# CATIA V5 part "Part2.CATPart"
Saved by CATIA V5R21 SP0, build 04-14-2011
Part number: Part2
Bounding box of the stored display mesh (mm): x 0 to 0, y -56.995 to 56.995, z -59.99 to 80.99
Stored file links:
  C:\Users\RIAD MAHAMUD PIASH\Desktop\Part2.CATPart
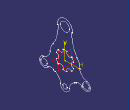
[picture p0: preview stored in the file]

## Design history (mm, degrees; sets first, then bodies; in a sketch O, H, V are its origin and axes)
Body1 (main body)
  Sketch1 on yz-plane, origin (0, 0, 0), H (0, 1, 0), V (0, 0, 1)
    circle A1 centre (0, 65) radius 10
    point P1 (0, 65)
    arc A2 centre (0, 65) radius 16 from (15.5763, 61.3421) to (-15.5763, 61.3421) ccw
    circle A3 centre (47, -26) radius 7
    point P2 (47, -26)
    circle A4 centre (-47, -26) radius 7
    circle A5 centre (0, -50) radius 5
    point P4 (0, -50)
    arc A6 centre (0, 0) radius 20 from (-19.1, -5.9321) to (-14.6874, -13.575) ccw
    arc A7 centre (47, -26) radius 10 from (38.6404, -31.4878) to (48.9509, -16.1921) ccw
    arc A8 centre (-47, -26) radius 10 from (-38.6404, -31.4878) to (-48.9509, -16.1921) cw
    arc A9 centre (0, -50) radius 10 from (-9.9672, -49.1912) to (9.9672, -49.1912) ccw
    arc A10 centre (0, 0) radius 33 from (-26.9908, 18.9867) to (-32.9789, 1.1809) ccw
    point P6 (-32.7768, -3.8319)
    arc A11 centre (-52.8527, 3.4236) radius 20 from (-48.9509, -16.1921) to (-32.9789, 1.1809) ccw
    point P8 (-48.9509, -16.1921)
    point P9 (-32.8556, 3.0836)
    arc A12 centre (-79.3367, 55.8094) radius 64 from (-15.5763, 61.3421) to (-26.9908, 18.9867) cw
    point P11 (-26.9908, 18.9867)
    point P12 (-32.9789, 1.1809)
    point P13 (26.9908, 18.9867)
    arc A13 centre (79.3367, 55.8094) radius 64 from (15.5763, 61.3421) to (26.9908, 18.9867) ccw
    point P15 (32.9789, 1.1809)
    arc A14 centre (0, 0) radius 33 from (26.9908, 18.9867) to (32.9789, 1.1809) cw
    point P17 (48.9509, -16.1921)
    arc A15 centre (52.8527, 3.4236) radius 20 from (48.9509, -16.1921) to (32.9789, 1.1809) cw
    point P19 (9.9672, -49.1912)
    arc A16 centre (29.9133, -50.6586) radius 20 from (9.9672, -49.1912) to (21.5794, -32.4777) cw
    arc A17 centre (31.2496, -38.3257) radius 10 from (25.3174, -30.2753) to (37.7472, -30.7243) cw
    point P22 (37.7472, -30.7243)
    arc A18 centre (12.7551, -13.2271) radius 21.1767 from (25.3174, -30.2753) to (21.5794, -32.4777) cw
    point P23 (25.3174, -30.2753)
    point P24 (21.5794, -32.4777)
    point P26 (-21.5794, -32.4777)
    point P27 (-9.9672, -49.1912)
    arc A19 centre (-29.9133, -50.6586) radius 20 from (-9.9672, -49.1912) to (-21.5794, -32.4777) ccw
    point P29 (-37.7472, -30.7243)
    point P30 (-25.3174, -30.2753)
    arc A20 centre (-31.2496, -38.3257) radius 10 from (-25.3174, -30.2753) to (-37.7472, -30.7243) ccw
    point P32 (-21.5794, -32.4777)
    point P33 (-25.3174, -30.2753)
    arc A21 centre (-12.7551, -13.2271) radius 21.1767 from (-25.3174, -30.2753) to (-21.5794, -32.4777) ccw
    line L1 (37.7472, -30.7243) -> (38.6404, -31.4878)
    point P35 (38.6404, -31.4878)
    point P36 (-38.6404, -31.4878)
    point P37 (-37.7472, -30.7243)
    line L2 (-37.7472, -30.7243) -> (-38.6404, -31.4878)
    arc A22 centre (-20, 0) radius 6 from (-19.1, -5.9321) to (-19.1, 5.9321) ccw
    point P40 (-20, 0)
    arc A23 centre (-10, -17.3205) radius 6 from (-4.4126, -19.5071) to (-14.6874, -13.575) ccw
    arc A24 centre (10, -17.3205) radius 6 from (14.6874, -13.575) to (4.4126, -19.5071) ccw
    arc A25 centre (20, 0) radius 6 from (19.1, 5.9321) to (19.1, -5.9321) ccw
    arc A26 centre (10, 17.3205) radius 6 from (4.4126, 19.5071) to (14.6874, 13.575) ccw
    arc A27 centre (-10, 17.3205) radius 6 from (-14.6874, 13.575) to (-4.4126, 19.5071) ccw
    arc A28 centre (0, 0) radius 20 from (-14.6874, 13.575) to (-19.1, 5.9321) ccw
    arc A29 centre (0, 0) radius 20 from (4.4126, 19.5071) to (-4.4126, 19.5071) ccw
    arc A30 centre (0, 0) radius 20 from (19.1, 5.9321) to (14.6874, 13.575) ccw
    arc A31 centre (0, 0) radius 20 from (14.6874, -13.575) to (19.1, -5.9321) ccw
    arc A32 centre (0, 0) radius 20 from (-4.4126, -19.5071) to (4.4126, -19.5071) ccw
    radius A1 = 10
    radius A2 = 16
    radius A3 = 7
    distance P2 H = 26
    distance P2 V = 47
    radius A5 = 5
    distance H P4 = 50
    distance P1 H = 65
    radius A6 = 20
    radius A7 = 10
    radius A9 = 10
    radius A10 = 33
    radius A11 = 20
    radius A12 = 64
    radius A17 = 10
    radius A16 = 20
    radius A18 = 21.1767
    radius A22 = 6
    coincidence: P1 V, P4 V, P6 A10, P9 A10, P40 A6, P40 H, A6 A28, A6 A29, A6 A30, A6 A31, A6 A32
    symmetry: A3 A4 V, A7 A8 V, P11 P13 V, A12 A13 V, P12 P15 V, A10 A14 V, P8 P17 V, A11 A15 V, P24 P26 V, P19 P27 V, A16 A19 V, P22 P29 V, P23 P30 V, A17 A20 V, P24 P32 V, P23 P33 V, A18 A21 V, P35 P36 V, P22 P37 V, L1 L2 V
    tangency: A11 A8, A12 A10, A16 A7, A17 A7, A18 A17, A18 A16, L1 A17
